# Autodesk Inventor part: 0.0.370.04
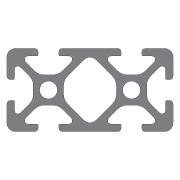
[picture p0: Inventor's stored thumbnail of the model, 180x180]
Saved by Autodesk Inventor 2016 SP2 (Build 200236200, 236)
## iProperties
Category: natur
Company: CAD Team Handzik
Created: 2017-10
Part Number: 0.0.370.04
Document SubType Name: Modeling
Designer: CAD Team Handzik
Density: 1 g/cm^3
Material: Allgemein
Vendor: Item
Appearance: Vorgabe
Description: Profil 5 40x20
MT_KOPF: =<CPR_ZEICHNR> - <CPR_SHORT>
Title: Profil 5 40x20
Subject: Muster für iPart Modul
Author: CAD Team Handzik
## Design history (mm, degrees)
node "Startebene"
node "Endebene"
sketch "Skizze1"
  geometry: L1 (21.618, -1.8)-(19.5, -1.8) reference; L2 (20, 0)-(24.7, 0) reference; L3 (13.9, -1.8)-(11.782, -1.8) reference; L4 (11.194, -3.221)-(13.444, -5.471) reference; L5 (12.171, -6.744)-(8.114, -2.687) reference; L6 (0, 0)-(13.4, 0) reference; L7 (5.286, -2.687)-(1.229, -6.744) reference; L8 (-6.1, -1.8)-(-8.218, -1.8) reference; L9 (-5.8, -0.8)-(-5.8, -1.5) reference; L10 (11.782, -18.2)-(13.9, -18.2) reference; L11 (14.2, -18.5)-(14.2, -19.2) reference; L12 (13.05, -11.135)-(13.05, -8.865) reference; L13 (17.835, -13.65)-(15.565, -13.65) reference; L14 (21.229, -13.256)-(23.479, -15.506) reference; L15 (24.9, -14.918)-(24.9, -12.8) reference; L16 (25.2, -12.5)-(25.9, -12.5) reference; L17 (22.206, -16.779)-(19.956, -14.529) reference; L18 (26.7, -13.3)-(26.7, -18) reference; L19 (19.5, -18.2)-(21.618, -18.2) reference; L20 (19.2, -19.2)-(19.2, -18.5) reference; L21 (24.7, -20)-(20, -20) reference; L22 (0.35, -8.865)-(0.35, -11.135) reference; L23 (-4.435, -6.35)-(-2.165, -6.35) reference; L24 (-0.8, -1.5)-(-0.8, -0.8) reference; L25 (1.618, -1.8)-(-0.5, -1.8) reference; L26 (-0.044, -5.471)-(2.206, -3.221) reference; L27 (8.114, -17.313)-(12.171, -13.256) reference; L28 (1.229, -13.256)-(5.286, -17.313) reference; L29 (13.4, -20)-(0, -20) reference; L30 (13.444, -14.529)-(11.194, -16.779) reference; L31 (-8.806, -3.221)-(-6.556, -5.471) reference; L32 (-11.3, 0)-(-6.6, 0) reference; L33 (-7.829, -6.744)-(-10.079, -4.494) reference; L34 (-13.3, -6.7)-(-13.3, -2) reference; L35 (-11.5, -5.082)-(-11.5, -7.2) reference; L36 (-11.8, -7.5)-(-12.5, -7.5) reference; L37 (-6.95, -11.135)-(-6.95, -8.865) reference; L38 (-12.5, -12.5)-(-11.8, -12.5) reference; L39 (-0.8, -19.2)-(-0.8, -18.5) reference; L40 (-0.5, -18.2)-(1.618, -18.2) reference; L41 (2.206, -16.779)-(-0.044, -14.529) reference; L42 (-2.165, -13.65)-(-4.435, -13.65) reference; L43 (14.2, -0.8)-(14.2, -1.5) reference; L44 (15.565, -6.35)-(17.835, -6.35) reference; L45 (19.2, -1.5)-(19.2, -0.8) reference; L46 (-11.5, -12.8)-(-11.5, -14.918) reference; L47 (-10.079, -15.506)-(-7.829, -13.256) reference; L48 (-6.556, -14.529)-(-8.806, -16.779) reference; L49 (-13.3, -18)-(-13.3, -13.3) reference; L50 (-8.218, -18.2)-(-6.1, -18.2) reference; L51 (-6.6, -20)-(-11.3, -20) reference; L52 (-5.8, -18.5)-(-5.8, -19.2) reference; L53 (26.7, -2)-(26.7, -6.7) reference; L54 (25.9, -7.5)-(25.2, -7.5) reference; L55 (24.9, -7.2)-(24.9, -5.082) reference; L56 (23.479, -4.494)-(21.229, -6.744) reference; L57 (20.35, -8.865)-(20.35, -11.135) reference; L58 (19.956, -5.471)-(22.206, -3.221) reference; C1 r 2.15 at (16.7, -10) reference; C2 r 2.15 at (-3.3, -10) reference; A1 r 0.832 centre (21.618, -2.632) between (22.206, -3.221) and (21.618, -1.8) reference; A2 r 2 centre (24.7, -2) between (26.7, -2) and (24.7, 0) reference; A3 r 3 centre (10.05, -8.865) between (13.05, -8.865) and (12.171, -6.744) reference; A4 r 0.832 centre (11.782, -2.632) between (11.782, -1.8) and (11.194, -3.221) reference; A5 r 2 centre (6.7, -4.101) between (8.114, -2.687) and (5.286, -2.687) reference; A6 r 3 centre (-4.435, -3.35) between (-6.556, -5.471) and (-4.435, -6.35) reference; A7 r 0.3 centre (-6.1, -1.5) between (-6.1, -1.8) and (-5.8, -1.5) reference; A8 r 0.8 centre (-6.6, -0.8) between (-5.8, -0.8) and (-6.6, 0) reference; A9 r 0.8 centre (13.4, -19.2) between (13.4, -20) and (14.2, -19.2) reference; A10 r 0.3 centre (13.9, -18.5) between (14.2, -18.5) and (13.9, -18.2) reference; A11 r 3 centre (10.05, -11.135) between (12.171, -13.256) and (13.05, -11.135) reference; A12 r 3 centre (15.565, -16.65) between (15.565, -13.65) and (13.444, -14.529) reference; A13 r 0.3 centre (19.5, -18.5) between (19.5, -18.2) and (19.2, -18.5) reference; A14 r 3 centre (17.835, -16.65) between (19.956, -14.529) and (17.835, -13.65) reference; A15 r 0.3 centre (25.2, -12.8) between (25.2, -12.5) and (24.9, -12.8) reference; A16 r 0.8 centre (25.9, -13.3) between (26.7, -13.3) and (25.9, -12.5) reference; A17 r 0.832 centre (24.068, -14.918) between (23.479, -15.506) and (24.9, -14.918) reference; A18 r 0.832 centre (21.618, -17.368) between (21.618, -18.2) and (22.206, -16.779) reference; A19 r 0.8 centre (20, -19.2) between (19.2, -19.2) and (20, -20) reference; A20 r 2 centre (24.7, -18) between (24.7, -20) and (26.7, -18) reference; A21 r 3 centre (3.35, -11.135) between (0.35, -11.135) and (1.229, -13.256) reference; A22 r 3 centre (3.35, -8.865) between (1.229, -6.744) and (0.35, -8.865) reference; A23 r 0.8 centre (0, -0.8) between (0, 0) and (-0.8, -0.8) reference; A24 r 0.3 centre (-0.5, -1.5) between (-0.8, -1.5) and (-0.5, -1.8) reference; A25 r 3 centre (-2.165, -3.35) between (-2.165, -6.35) and (-0.044, -5.471) reference; A26 r 0.832 centre (1.618, -2.632) between (2.206, -3.221) and (1.618, -1.8) reference; A27 r 0.832 centre (11.782, -17.368) between (11.194, -16.779) and (11.782, -18.2) reference; A28 r 2 centre (6.7, -15.899) between (5.286, -17.313) and (8.114, -17.313) reference; A29 r 0.832 centre (-8.218, -2.632) between (-8.218, -1.8) and (-8.806, -3.221) reference; A30 r 2 centre (-11.3, -2) between (-11.3, 0) and (-13.3, -2) reference; A31 r 0.832 centre (-10.668, -5.082) between (-10.079, -4.494) and (-11.5, -5.082) reference; A32 r 0.8 centre (-12.5, -6.7) between (-13.3, -6.7) and (-12.5, -7.5) reference; A33 r 0.3 centre (-11.8, -7.2) between (-11.8, -7.5) and (-11.5, -7.2) reference; A34 r 3 centre (-9.95, -8.865) between (-6.95, -8.865) and (-7.829, -6.744) reference; A35 r 3 centre (-9.95, -11.135) between (-7.829, -13.256) and (-6.95, -11.135) reference; A36 r 0.3 centre (-11.8, -12.8) between (-11.5, -12.8) and (-11.8, -12.5) reference; A37 r 0.8 centre (-12.5, -13.3) between (-12.5, -12.5) and (-13.3, -13.3) reference; A38 r 0.3 centre (-0.5, -18.5) between (-0.5, -18.2) and (-0.8, -18.5) reference; A39 r 0.8 centre (0, -19.2) between (-0.8, -19.2) and (0, -20) reference; A40 r 3 centre (-2.165, -16.65) between (-0.044, -14.529) and (-2.165, -13.65) reference; A41 r 0.832 centre (1.618, -17.368) between (1.618, -18.2) and (2.206, -16.779) reference; A42 r 0.8 centre (13.4, -0.8) between (14.2, -0.8) and (13.4, 0) reference; A43 r 0.3 centre (13.9, -1.5) between (13.9, -1.8) and (14.2, -1.5) reference; A44 r 3 centre (15.565, -3.35) between (13.444, -5.471) and (15.565, -6.35) reference; A45 r 3 centre (17.835, -3.35) between (17.835, -6.35) and (19.956, -5.471) reference; A46 r 0.3 centre (19.5, -1.5) between (19.2, -1.5) and (19.5, -1.8) reference; A47 r 0.8 centre (20, -0.8) between (20, 0) and (19.2, -0.8) reference; A48 r 0.832 centre (-10.668, -14.918) between (-11.5, -14.918) and (-10.079, -15.506) reference; A49 r 0.832 centre (-8.218, -17.368) between (-8.806, -16.779) and (-8.218, -18.2) reference; A50 r 2 centre (-11.3, -18) between (-13.3, -18) and (-11.3, -20) reference; A51 r 0.3 centre (-6.1, -18.5) between (-5.8, -18.5) and (-6.1, -18.2) reference; A52 r 0.8 centre (-6.6, -19.2) between (-6.6, -20) and (-5.8, -19.2) reference; A53 r 3 centre (-4.435, -16.65) between (-4.435, -13.65) and (-6.556, -14.529) reference; A54 r 0.832 centre (24.068, -5.082) between (24.9, -5.082) and (23.479, -4.494) reference; A55 r 0.8 centre (25.9, -6.7) between (25.9, -7.5) and (26.7, -6.7) reference; A56 r 0.3 centre (25.2, -7.2) between (24.9, -7.2) and (25.2, -7.5) reference; A57 r 3 centre (23.35, -8.865) between (21.229, -6.744) and (20.35, -8.865) reference; A58 r 3 centre (23.35, -11.135) between (20.35, -11.135) and (21.229, -13.256) reference
  constraints: 116 end point, 116 point on circle, 60 centre point, 22 horizontal, 20 vertical, 252 other
extrude "Extrusion3" new body sketch "Skizze1" stored distance "d8" = 10; taper "d9" = 0 deg
node "Volumenkörper2"
node "Volumenkörper"
node "Flächenkörper"
other parameters: "d2" = -25 (= -0.5 x LANG), "d3" = 25 (= 0.5 x LANG)
